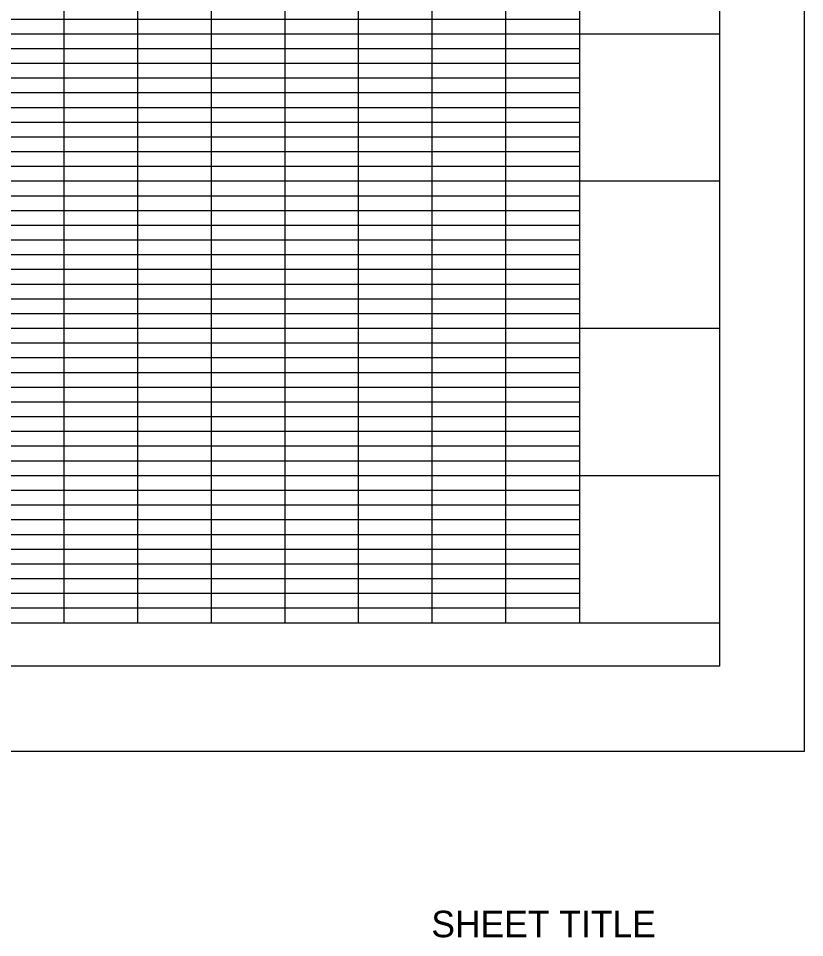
# Model space of a CAD drawing. Extents: x 0 to 19, y -0.6 to 11.2.
# Drawn here: x 14.329 to 17, y -0.633 to 2.489 of the extents above; entities that cross this region are included whole.
import ezdxf

# ---------------------------------------------------------------- set-up
doc = ezdxf.new("R2010")
doc.units = 0
for name, color, linetype in [('G-ANNO-TEXT', 7, 'Continuous'), ('G-Border-Paper', 7, 'Continuous'), ('G-Border-Sheet', 7, 'Continuous'), ('G-Grid-Border', 7, 'Continuous'), ('G-Grid-Major', 7, 'Continuous'), ('G-Grid-Minor', 7, 'Continuous')]:
    doc.layers.add(name, color=color, linetype=linetype)

msp = doc.modelspace()

# ---------------------------------------------------------------- linework, layer by layer
at = {"layer": 'G-Border-Paper'}
msp.add_lwpolyline([(17, 11), (0, 11), (0, 0), (17, 0)], close=True, dxfattribs=at)
at = {"layer": 'G-Border-Sheet'}
for q in [(16.7116, 10.7116), (0.758, 0.2884)]:
    msp.add_line((16.7116, 0.2884), q, dxfattribs=at)
at = {"layer": 'G-Grid-Border'}
msp.add_line((16.7116, 0.4354), (0.758, 0.4354), dxfattribs=at)
msp.add_lwpolyline([(1.2348, 5.4354), (16.2348, 5.4354), (16.2348, 0.4354), (1.2348, 0.4354)], close=True, dxfattribs=at)
at = {"layer": 'G-Grid-Major'}
for p, q in [((14.7348, 0.4354), (14.7348, 5.4354)), ((15.2348, 0.4354), (15.2348, 5.4354)), ((15.7348, 0.4354), (15.7348, 5.4354)), ((16.7116, 2.4354), (0.758, 2.4354)), ((16.7116, 1.9354), (0.758, 1.9354)), ((16.7116, 1.4354), (0.758, 1.4354)), ((16.7116, 0.9354), (0.758, 0.9354))]:
    msp.add_line(p, q, dxfattribs=at)
msp.add_lwpolyline([(1.2348, 5.4354), (16.2348, 5.4354), (16.2348, 0.4354), (1.2348, 0.4354)], close=True, dxfattribs=at)
at = {"layer": 'G-Grid-Minor'}
for p, q in [((14.4848, 0.4354), (14.4848, 5.4354)), ((14.9848, 0.4354), (14.9848, 5.4354)), ((15.4848, 0.4354), (15.4848, 5.4354)), ((15.9848, 0.4354), (15.9848, 5.4354)), ((16.2348, 2.4854), (1.2348, 2.4854)), ((16.2348, 2.3854), (1.2348, 2.3854)), ((16.2348, 2.3354), (1.2348, 2.3354)), ((16.2348, 2.2854), (1.2348, 2.2854)), ((16.2348, 2.2354), (1.2348, 2.2354)), ((16.2348, 2.1854), (1.2348, 2.1854)), ((16.2348, 2.1354), (1.2348, 2.1354)), ((16.2348, 2.0854), (1.2348, 2.0854)), ((16.2348, 2.0354), (1.2348, 2.0354)), ((16.2348, 1.9854), (1.2348, 1.9854)), ((16.2348, 1.8854), (1.2348, 1.8854)), ((16.2348, 1.8354), (1.2348, 1.8354)), ((16.2348, 1.7854), (1.2348, 1.7854)), ((16.2348, 1.7354), (1.2348, 1.7354)), ((16.2348, 1.6854), (1.2348, 1.6854)), ((16.2348, 1.6354), (1.2348, 1.6354)), ((16.2348, 1.5854), (1.2348, 1.5854)), ((16.2348, 1.5354), (1.2348, 1.5354)), ((16.2348, 1.4854), (1.2348, 1.4854)), ((16.2348, 1.3854), (1.2348, 1.3854)), ((16.2348, 1.3354), (1.2348, 1.3354)), ((16.2348, 1.2854), (1.2348, 1.2854)), ((16.2348, 1.2354), (1.2348, 1.2354)), ((16.2348, 1.1854), (1.2348, 1.1854)), ((16.2348, 1.1354), (1.2348, 1.1354)), ((16.2348, 1.0854), (1.2348, 1.0854)), ((16.2348, 1.0354), (1.2348, 1.0354)), ((16.2348, 0.9854), (1.2348, 0.9854)), ((16.2348, 0.8854), (1.2348, 0.8854)), ((16.2348, 0.8354), (1.2348, 0.8354)), ((16.2348, 0.7854), (1.2348, 0.7854)), ((16.2348, 0.7354), (1.2348, 0.7354)), ((16.2348, 0.6854), (1.2348, 0.6854)), ((16.2348, 0.6354), (1.2348, 0.6354)), ((16.2348, 0.5854), (1.2348, 0.5854)), ((16.2348, 0.5354), (1.2348, 0.5354)), ((16.2348, 0.4854), (1.2348, 0.4854))]:
    msp.add_line(p, q, dxfattribs=at)

# ---------------------------------------------------------------- texts
at = {"layer": 'G-ANNO-TEXT'}
msp.add_text('SHEET TITLE', height=0.09, dxfattribs=at).set_placement((15.7319, -0.6318))

doc.saveas('drawing.dxf')
